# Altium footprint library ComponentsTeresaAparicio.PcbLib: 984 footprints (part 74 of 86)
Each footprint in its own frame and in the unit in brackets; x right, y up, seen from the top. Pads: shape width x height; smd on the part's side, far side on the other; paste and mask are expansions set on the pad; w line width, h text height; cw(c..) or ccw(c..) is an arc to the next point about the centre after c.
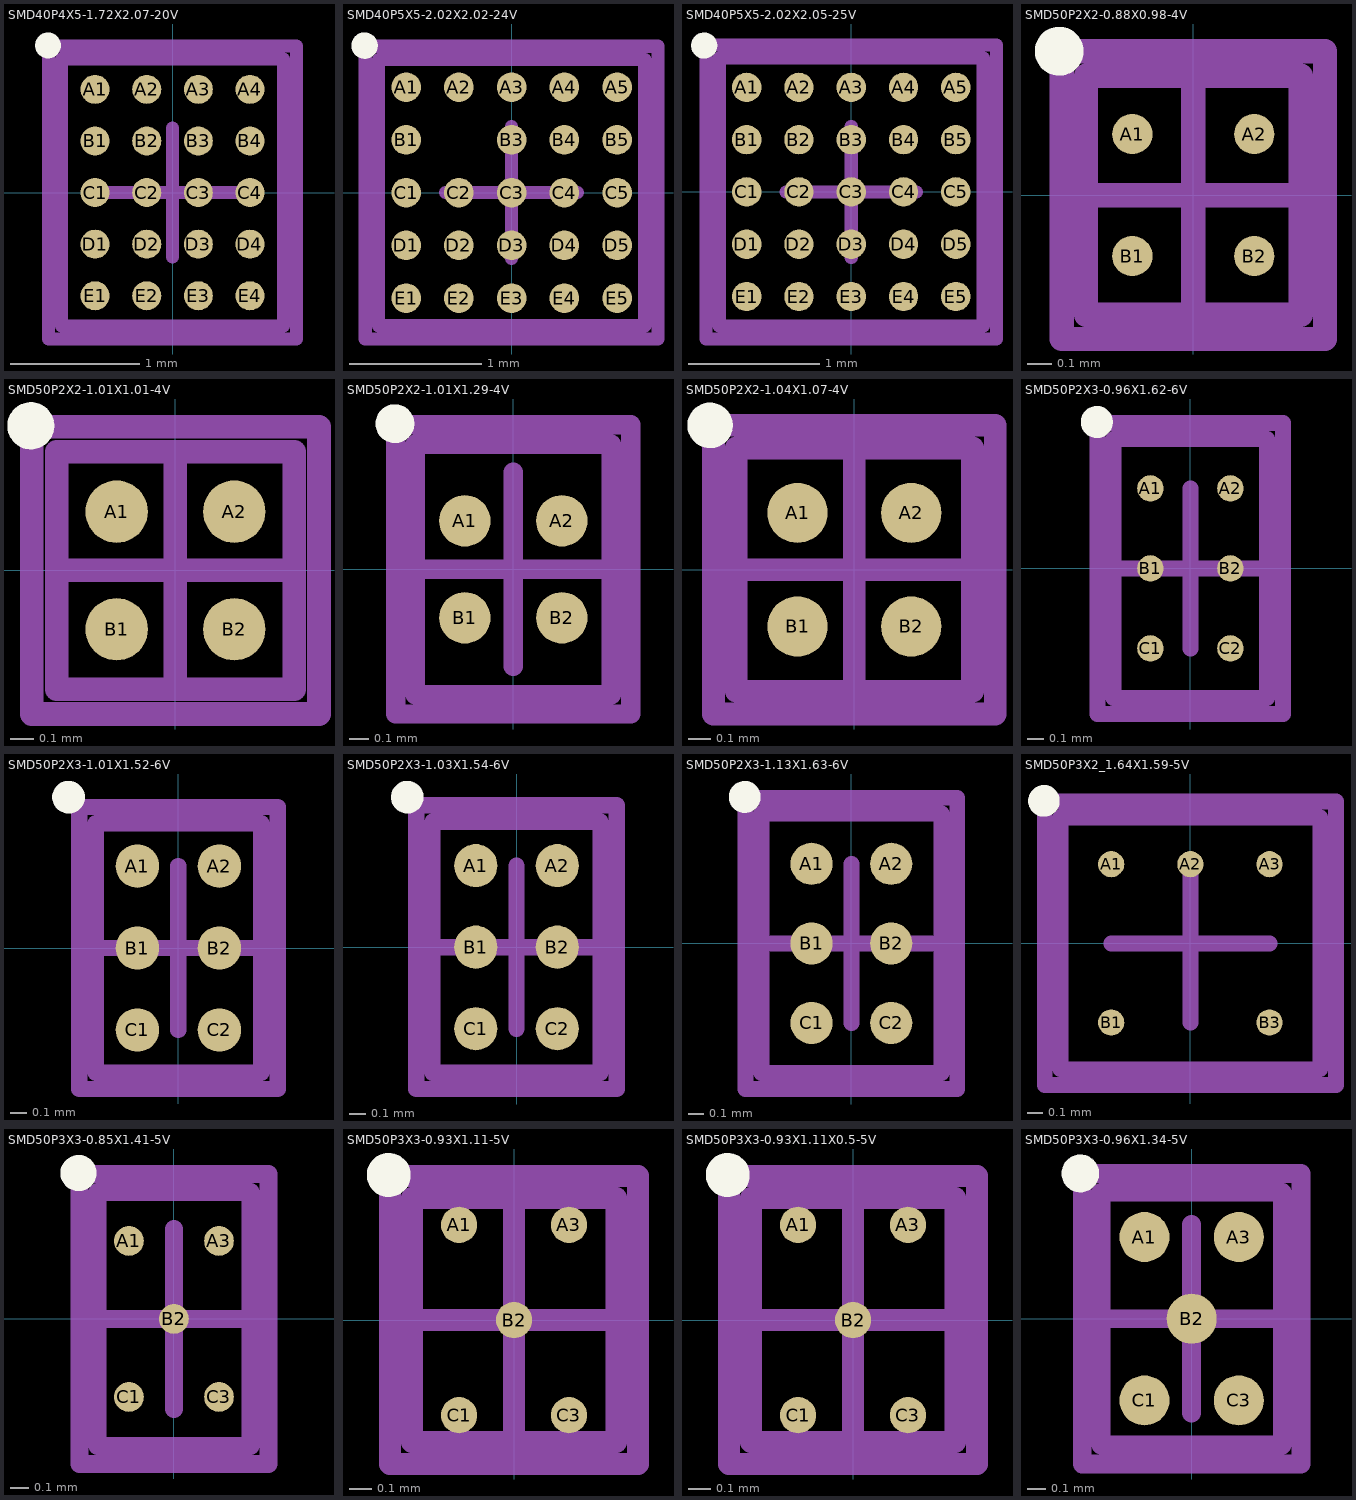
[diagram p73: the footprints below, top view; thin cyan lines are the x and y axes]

## SMD40P4X5-1.72X2.07-20V [mm] "Micro SMD, 20-Leads, Body 2.07x1.72mm, Pitch 0.4mm, NSC Recommended"
height 0.68
pads (20):
  round 0.225 smd paste-0.112 mask+0.05: A1(-0.6,0.8) A2(-0.2,0.8) A3(0.2,0.8) A4(0.6,0.8) B1(-0.6,0.4) B2(-0.2,0.4) B3(0.2,0.4) B4(0.6,0.4) C1(-0.6,0) C2(-0.2,0) C3(0.2,0) C4(0.6,0) D1(-0.6,-0.4) D2(-0.2,-0.4) D3(0.2,-0.4) D4(0.6,-0.4) E1(-0.6,-0.8) E2(-0.2,-0.8) E3(0.2,-0.8) E4(0.6,-0.8)
Top Overlay:
  circle w0.1: c-0.965,1.14 r0.05
Top Paste:
  drawing of 180 lines, arcs and shapes, not listed
Mechanical 13:
  lines w0.1: -0.86,-1.035 0.86,-1.035 0.86,1.035 -0.86,1.035 -0.86,-1.035
Mechanical 15:
  lines w0.1: -0.5,0 0.5,0 ; 0,-0.5 0,0.5 ; -0.96,-1.135 0.96,-1.135 0.96,1.135 -0.96,1.135 -0.96,-1.135
3D body: height 0.68, standoff 0, extent -0.86,-1.035 0.86,1.035

## SMD40P5X5-2.02X2.02-24V [mm] "Micro SMD, 24-Leads, Body 2.02x2.02mm, Pitch 0.4mm, NSC Recommended"
height 0.68
pads (24):
  round 0.225 smd paste-0.112 mask+0.05: A1(-0.8,0.8) A2(-0.4,0.8) A3(0,0.8) A4(0.4,0.8) A5(0.8,0.8) B1(-0.8,0.4) B3(0,0.4) B4(0.4,0.4) B5(0.8,0.4) C1(-0.8,0) C2(-0.4,0) C3(0,0) C4(0.4,0) C5(0.8,0) D1(-0.8,-0.4) D2(-0.4,-0.4) D3(0,-0.4) D4(0.4,-0.4) D5(0.8,-0.4) E1(-0.8,-0.8) E2(-0.4,-0.8) E3(0,-0.8) E4(0.4,-0.8) E5(0.8,-0.8)
Top Overlay:
  circle w0.1: c-1.115,1.115 r0.05
Top Paste:
  drawing of 216 lines, arcs and shapes, not listed
Mechanical 13:
  lines w0.1: -1.01,-1.01 -1.01,1.01 1.01,1.01 1.01,-1.01 -1.01,-1.01
Mechanical 15:
  lines w0.1: -0.5,0 0.5,0 ; 0,-0.5 0,0.5 ; -1.11,-1.11 -1.11,1.11 1.11,1.11 1.11,-1.11 -1.11,-1.11
3D body: height 0.68, standoff 0, extent -1.01,-1.01 1.01,1.01

## SMD40P5X5-2.02X2.05-25V [mm] "Micro SMD, 25-Leads, Body 2.05x2.02mm, Pitch 0.4mm, NSC Recommended"
height 0.68
pads (25):
  round 0.225 smd paste-0.112 mask+0.05: A1(-0.8,0.8) A2(-0.4,0.8) A3(0,0.8) A4(0.4,0.8) A5(0.8,0.8) B1(-0.8,0.4) B2(-0.4,0.4) B3(0,0.4) B4(0.4,0.4) B5(0.8,0.4) C1(-0.8,0) C2(-0.4,0) C3(0,0) C4(0.4,0) C5(0.8,0) D1(-0.8,-0.4) D2(-0.4,-0.4) D3(0,-0.4) D4(0.4,-0.4) D5(0.8,-0.4) E1(-0.8,-0.8) E2(-0.4,-0.8) E3(0,-0.8) E4(0.4,-0.8) E5(0.8,-0.8)
Top Overlay:
  circle w0.1: c-1.125,1.12 r0.05
Top Paste:
  drawing of 225 lines, arcs and shapes, not listed
Mechanical 13:
  lines w0.1: -1.01,-1.025 1.01,-1.025 1.01,1.025 -1.01,1.025 -1.01,-1.025
Mechanical 15:
  lines w0.1: -0.5,0 0.5,0 ; 0,-0.5 0,0.5 ; -1.11,-1.125 1.11,-1.125 1.11,1.125 -1.11,1.125 -1.11,-1.125
3D body: height 0.68, standoff 0, extent -1.009,-1.024 1.009,1.024

## SMD50P2X2-0.88X0.98-4V [mm] "Micro SMD, 4-Leads, Body 0.98x0.88mm, Pitch 0.5mm, NSC Recommended"
height 0.58
pads (4):
  round 0.165 smd paste-0.082 mask+0.05: A1(-0.25,0.25) A2(0.25,0.25) B1(-0.25,-0.25) B2(0.25,-0.25)
Top Overlay:
  circle w0.1: c-0.55,0.59 r0.05
Top Paste:
  circle w0.05: c0.175,0.175 r0.025
  circle w0.05: c0.375,0.375 r0.025
  circle w0.05: c0.175,0.375 r0.025
  circle w0.05: c0.375,0.175 r0.025
  circle w0.05: c0.175,-0.175 r0.025
  circle w0.05: c0.375,-0.375 r0.025
  circle w0.05: c0.375,-0.175 r0.025
  circle w0.05: c0.175,-0.375 r0.025
  circle w0.05: c-0.175,-0.175 r0.025
  circle w0.05: c-0.375,-0.375 r0.025
  circle w0.05: c-0.175,-0.375 r0.025
  circle w0.05: c-0.375,-0.175 r0.025
  circle w0.05: c-0.175,0.175 r0.025
  circle w0.05: c-0.375,0.375 r0.025
  circle w0.05: c-0.375,0.175 r0.025
  circle w0.05: c-0.175,0.375 r0.025
  region: 0.125,0.375 0.125,0.175 0.175,0.175 0.175,0.375
  region: 0.425,0.175 0.425,0.375 0.375,0.375 0.375,0.175
  region: 0.375,0.425 0.175,0.425 0.175,0.375 0.375,0.375
  region: 0.375,0.375 0.175,0.375 0.175,0.175 0.375,0.175
  rectangle: 0.175,0.125 0.375,0.175
  region: 0.375,-0.125 0.175,-0.125 0.175,-0.175 0.375,-0.175
  rectangle: 0.175,-0.425 0.375,-0.375
  region: 0.425,-0.375 0.425,-0.175 0.375,-0.175 0.375,-0.375
  region: 0.375,-0.375 0.375,-0.175 0.175,-0.175 0.175,-0.375
  region: 0.125,-0.175 0.125,-0.375 0.175,-0.375 0.175,-0.175
  region: -0.125,-0.375 -0.125,-0.175 -0.175,-0.175 -0.175,-0.375
  region: -0.425,-0.175 -0.425,-0.375 -0.375,-0.375 -0.375,-0.175
  rectangle: -0.375,-0.425 -0.175,-0.375
  rectangle: -0.375,-0.375 -0.175,-0.175
  region: -0.175,-0.125 -0.375,-0.125 -0.375,-0.175 -0.175,-0.175
  rectangle: -0.375,0.125 -0.175,0.175
  region: -0.175,0.425 -0.375,0.425 -0.375,0.375 -0.175,0.375
  region: -0.425,0.375 -0.425,0.175 -0.375,0.175 -0.375,0.375
  region: -0.375,0.375 -0.375,0.175 -0.175,0.175 -0.175,0.375
  region: -0.125,0.175 -0.125,0.375 -0.175,0.375 -0.175,0.175
Mechanical 13:
  lines w0.1: -0.44,-0.49 -0.44,0.49 0.44,0.49 0.44,-0.49 -0.44,-0.49
Mechanical 15:
  lines w0.1: -0.5,0 0.5,0 ; 0,-0.5 0,0.5 ; -0.54,-0.59 -0.54,0.59 0.54,0.59 0.54,-0.59 -0.54,-0.59
3D body: height 0.58, standoff 0, extent -0.439,-0.489 0.439,0.489

## SMD50P2X2-1.01X1.01-4V [mm] "Micro SMD, 4-Leads, Body 1.01x1.01mm, Pitch 0.5mm, NSC Recommended"
height 0.68
pads (4):
  round 0.265 smd paste-0.132 mask+0.05: A1(-0.25,0.25) A2(0.25,0.25) B1(-0.25,-0.25) B2(0.25,-0.25)
Top Overlay:
  circle w0.1: c-0.615,0.615 r0.05
Top Paste:
  circle w0.05: c-0.35,0.2 r0.025
  circle w0.05: c-0.2,0.35 r0.025
  circle w0.05: c-0.35,0.35 r0.025
  circle w0.05: c-0.2,0.2 r0.025
  circle w0.05: c-0.2,-0.35 r0.025
  circle w0.05: c-0.35,-0.2 r0.025
  circle w0.05: c-0.35,-0.35 r0.025
  circle w0.05: c-0.2,-0.2 r0.025
  circle w0.05: c0.35,-0.2 r0.025
  circle w0.05: c0.2,-0.35 r0.025
  circle w0.05: c0.35,-0.35 r0.025
  circle w0.05: c0.2,-0.2 r0.025
  circle w0.05: c0.2,0.35 r0.025
  circle w0.05: c0.35,0.2 r0.025
  circle w0.05: c0.35,0.35 r0.025
  circle w0.05: c0.2,0.2 r0.025
  region: -0.2,0.35 -0.2,0.2 -0.15,0.2 -0.15,0.35
  rectangle: -0.35,0.35 -0.2,0.4
  region: -0.35,0.2 -0.35,0.35 -0.4,0.35 -0.4,0.2
  region: -0.2,0.2 -0.35,0.2 -0.35,0.15 -0.2,0.15
  rectangle: -0.35,0.2 -0.2,0.35
  rectangle: -0.35,-0.2 -0.2,-0.15
  region: -0.35,-0.35 -0.35,-0.2 -0.4,-0.2 -0.4,-0.35
  region: -0.2,-0.35 -0.35,-0.35 -0.35,-0.4 -0.2,-0.4
  region: -0.2,-0.2 -0.2,-0.35 -0.15,-0.35 -0.15,-0.2
  region: -0.2,-0.35 -0.2,-0.2 -0.35,-0.2 -0.35,-0.35
  region: 0.2,-0.35 0.2,-0.2 0.15,-0.2 0.15,-0.35
  region: 0.35,-0.35 0.2,-0.35 0.2,-0.4 0.35,-0.4
  region: 0.35,-0.2 0.35,-0.35 0.4,-0.35 0.4,-0.2
  rectangle: 0.2,-0.2 0.35,-0.15
  region: 0.35,-0.2 0.2,-0.2 0.2,-0.35 0.35,-0.35
  region: 0.35,0.2 0.2,0.2 0.2,0.15 0.35,0.15
  region: 0.35,0.35 0.35,0.2 0.4,0.2 0.4,0.35
  rectangle: 0.2,0.35 0.35,0.4
  region: 0.2,0.2 0.2,0.35 0.15,0.35 0.15,0.2
  region: 0.2,0.35 0.2,0.2 0.35,0.2 0.35,0.35
Mechanical 13:
  lines w0.1: -0.505,-0.505 -0.505,0.505 0.505,0.505 0.505,-0.505 -0.505,-0.505
Mechanical 15:
  lines w0.1: -0.5,0 0.5,0 ; 0,-0.5 0,0.5 ; -0.61,-0.61 -0.61,0.61 0.61,0.61 0.61,-0.61 -0.61,-0.61
3D body: height 0.68, standoff 0, extent -0.504,-0.504 0.504,0.504

## SMD50P2X2-1.01X1.29-4V [mm] "Micro SMD, 4-Leads, Body 1.29x1.01mm, Pitch 0.5mm, NSC Recommended"
height 0.68
pads (4):
  round 0.265 smd paste-0.132 mask+0.05: A1(-0.25,0.25) A2(0.25,0.25) B1(-0.25,-0.25) B2(0.25,-0.25)
Top Overlay:
  circle w0.1: c-0.61,0.75 r0.05
Top Paste:
  circle w0.05: c-0.35,0.2 r0.025
  circle w0.05: c-0.2,0.35 r0.025
  circle w0.05: c-0.35,0.35 r0.025
  circle w0.05: c-0.2,0.2 r0.025
  circle w0.05: c-0.2,-0.35 r0.025
  circle w0.05: c-0.35,-0.2 r0.025
  circle w0.05: c-0.35,-0.35 r0.025
  circle w0.05: c-0.2,-0.2 r0.025
  circle w0.05: c0.35,-0.2 r0.025
  circle w0.05: c0.2,-0.35 r0.025
  circle w0.05: c0.35,-0.35 r0.025
  circle w0.05: c0.2,-0.2 r0.025
  circle w0.05: c0.2,0.35 r0.025
  circle w0.05: c0.35,0.2 r0.025
  circle w0.05: c0.35,0.35 r0.025
  circle w0.05: c0.2,0.2 r0.025
  region: -0.2,0.35 -0.2,0.2 -0.15,0.2 -0.15,0.35
  rectangle: -0.35,0.35 -0.2,0.4
  region: -0.35,0.2 -0.35,0.35 -0.4,0.35 -0.4,0.2
  region: -0.2,0.2 -0.35,0.2 -0.35,0.15 -0.2,0.15
  rectangle: -0.35,0.2 -0.2,0.35
  rectangle: -0.35,-0.2 -0.2,-0.15
  region: -0.35,-0.35 -0.35,-0.2 -0.4,-0.2 -0.4,-0.35
  region: -0.2,-0.35 -0.35,-0.35 -0.35,-0.4 -0.2,-0.4
  region: -0.2,-0.2 -0.2,-0.35 -0.15,-0.35 -0.15,-0.2
  region: -0.2,-0.35 -0.2,-0.2 -0.35,-0.2 -0.35,-0.35
  region: 0.2,-0.35 0.2,-0.2 0.15,-0.2 0.15,-0.35
  region: 0.35,-0.35 0.2,-0.35 0.2,-0.4 0.35,-0.4
  region: 0.35,-0.2 0.35,-0.35 0.4,-0.35 0.4,-0.2
  rectangle: 0.2,-0.2 0.35,-0.15
  region: 0.35,-0.2 0.2,-0.2 0.2,-0.35 0.35,-0.35
  region: 0.35,0.2 0.2,0.2 0.2,0.15 0.35,0.15
  region: 0.35,0.35 0.35,0.2 0.4,0.2 0.4,0.35
  rectangle: 0.2,0.35 0.35,0.4
  region: 0.2,0.2 0.2,0.35 0.15,0.35 0.15,0.2
  region: 0.2,0.35 0.2,0.2 0.35,0.2 0.35,0.35
Mechanical 13:
  lines w0.1: -0.505,-0.645 -0.505,0.645 0.505,0.645 0.505,-0.645 -0.505,-0.645
Mechanical 15:
  lines w0.1: -0.5,0 0.5,0 ; 0,-0.5 0,0.5 ; -0.605,-0.745 -0.605,0.745 0.605,0.745 0.605,-0.745 -0.605,-0.745
3D body: height 0.68, standoff 0, extent -0.504,-0.644 0.504,0.644

## SMD50P2X2-1.04X1.07-4V [mm] "Micro SMD, 4-Leads, Body 1.07x1.04mm, Pitch 0.5mm, NSC Recommended"
height 0.68
pads (4):
  round 0.265 smd paste-0.132 mask+0.05: A1(-0.25,0.25) A2(0.25,0.25) B1(-0.25,-0.25) B2(0.25,-0.25)
Top Overlay:
  circle w0.1: c-0.635,0.635 r0.05
Top Paste:
  circle w0.05: c0.2,0.2 r0.025
  circle w0.05: c0.35,0.35 r0.025
  circle w0.05: c0.35,0.2 r0.025
  circle w0.05: c0.2,0.35 r0.025
  circle w0.05: c0.2,-0.2 r0.025
  circle w0.05: c0.35,-0.35 r0.025
  circle w0.05: c0.2,-0.35 r0.025
  circle w0.05: c0.35,-0.2 r0.025
  circle w0.05: c-0.2,-0.2 r0.025
  circle w0.05: c-0.35,-0.35 r0.025
  circle w0.05: c-0.35,-0.2 r0.025
  circle w0.05: c-0.2,-0.35 r0.025
  circle w0.05: c-0.2,0.2 r0.025
  circle w0.05: c-0.35,0.35 r0.025
  circle w0.05: c-0.2,0.35 r0.025
  circle w0.05: c-0.35,0.2 r0.025
  region: 0.2,0.35 0.2,0.2 0.35,0.2 0.35,0.35
  region: 0.2,0.2 0.2,0.35 0.15,0.35 0.15,0.2
  rectangle: 0.2,0.35 0.35,0.4
  region: 0.35,0.35 0.35,0.2 0.4,0.2 0.4,0.35
  region: 0.35,0.2 0.2,0.2 0.2,0.15 0.35,0.15
  region: 0.35,-0.2 0.2,-0.2 0.2,-0.35 0.35,-0.35
  rectangle: 0.2,-0.2 0.35,-0.15
  region: 0.35,-0.2 0.35,-0.35 0.4,-0.35 0.4,-0.2
  region: 0.35,-0.35 0.2,-0.35 0.2,-0.4 0.35,-0.4
  region: 0.2,-0.35 0.2,-0.2 0.15,-0.2 0.15,-0.35
  region: -0.2,-0.35 -0.2,-0.2 -0.35,-0.2 -0.35,-0.35
  region: -0.2,-0.2 -0.2,-0.35 -0.15,-0.35 -0.15,-0.2
  region: -0.2,-0.35 -0.35,-0.35 -0.35,-0.4 -0.2,-0.4
  region: -0.35,-0.35 -0.35,-0.2 -0.4,-0.2 -0.4,-0.35
  rectangle: -0.35,-0.2 -0.2,-0.15
  rectangle: -0.35,0.2 -0.2,0.35
  region: -0.2,0.2 -0.35,0.2 -0.35,0.15 -0.2,0.15
  region: -0.35,0.2 -0.35,0.35 -0.4,0.35 -0.4,0.2
  rectangle: -0.35,0.35 -0.2,0.4
  region: -0.2,0.35 -0.2,0.2 -0.15,0.2 -0.15,0.35
Mechanical 13:
  lines w0.1: -0.52,-0.535 0.52,-0.535 0.52,0.535 -0.52,0.535 -0.52,-0.535
Mechanical 15:
  lines w0.1: -0.5,0 0.5,0 ; 0,-0.5 0,0.5 ; -0.62,-0.635 0.62,-0.635 0.62,0.635 -0.62,0.635 -0.62,-0.635
3D body: height 0.68, standoff 0, extent -0.519,-0.534 0.519,0.534

## SMD50P2X3-0.96X1.62-6V [mm] "Micro SMD, 6-Leads, Body 1.62x0.96mm, Pitch 0.5mm, NSC Recommended"
height 0.58
pads (6):
  round 0.165 smd paste-0.082 mask+0.05: A1(-0.25,0.5) A2(0.25,0.5) B1(-0.25,0) B2(0.25,0) C1(-0.25,-0.5) C2(0.25,-0.5)
Top Overlay:
  circle w0.1: c-0.585,0.915 r0.05
Top Paste:
  circle w0.05: c-0.175,0.425 r0.025
  circle w0.05: c-0.375,0.625 r0.025
  circle w0.05: c-0.175,0.625 r0.025
  circle w0.05: c-0.375,0.425 r0.025
  circle w0.05: c0.375,0.425 r0.025
  circle w0.05: c0.175,0.625 r0.025
  circle w0.05: c0.375,0.625 r0.025
  circle w0.05: c0.175,0.425 r0.025
  circle w0.05: c-0.175,-0.1 r0.025
  circle w0.05: c-0.375,0.1 r0.025
  circle w0.05: c-0.175,0.1 r0.025
  circle w0.05: c-0.375,-0.1 r0.025
  circle w0.05: c0.375,-0.1 r0.025
  circle w0.05: c0.175,0.1 r0.025
  circle w0.05: c0.375,0.1 r0.025
  circle w0.05: c0.175,-0.1 r0.025
  circle w0.05: c-0.175,-0.625 r0.025
  circle w0.05: c-0.375,-0.425 r0.025
  circle w0.05: c-0.175,-0.425 r0.025
  circle w0.05: c-0.375,-0.625 r0.025
  circle w0.05: c0.375,-0.625 r0.025
  circle w0.05: c0.175,-0.425 r0.025
  circle w0.05: c0.375,-0.425 r0.025
  circle w0.05: c0.175,-0.625 r0.025
  region: -0.175,0.625 -0.175,0.425 -0.125,0.425 -0.125,0.625
  region: -0.375,0.425 -0.375,0.625 -0.425,0.625 -0.425,0.425
  rectangle: -0.375,0.625 -0.175,0.675
  rectangle: -0.375,0.425 -0.175,0.625
  region: -0.175,0.425 -0.375,0.425 -0.375,0.375 -0.175,0.375
  region: 0.375,0.625 0.375,0.425 0.425,0.425 0.425,0.625
  region: 0.175,0.425 0.175,0.625 0.125,0.625 0.125,0.425
  rectangle: 0.175,0.625 0.375,0.675
  rectangle: 0.175,0.425 0.375,0.625
  region: 0.375,0.425 0.175,0.425 0.175,0.375 0.375,0.375
  region: -0.175,0.1 -0.175,-0.1 -0.125,-0.1 -0.125,0.1
  region: -0.375,-0.1 -0.375,0.1 -0.425,0.1 -0.425,-0.1
  rectangle: -0.375,0.1 -0.175,0.15
  rectangle: -0.375,-0.1 -0.175,0.1
  region: -0.175,-0.1 -0.375,-0.1 -0.375,-0.15 -0.175,-0.15
  region: 0.375,0.1 0.375,-0.1 0.425,-0.1 0.425,0.1
  region: 0.175,-0.1 0.175,0.1 0.125,0.1 0.125,-0.1
  rectangle: 0.175,0.1 0.375,0.15
  rectangle: 0.175,-0.1 0.375,0.1
  region: 0.375,-0.1 0.175,-0.1 0.175,-0.15 0.375,-0.15
  region: -0.175,-0.425 -0.175,-0.625 -0.125,-0.625 -0.125,-0.425
  region: -0.375,-0.625 -0.375,-0.425 -0.425,-0.425 -0.425,-0.625
  rectangle: -0.375,-0.425 -0.175,-0.375
  rectangle: -0.375,-0.625 -0.175,-0.425
  region: -0.175,-0.625 -0.375,-0.625 -0.375,-0.675 -0.175,-0.675
  region: 0.375,-0.425 0.375,-0.625 0.425,-0.625 0.425,-0.425
  region: 0.175,-0.625 0.175,-0.425 0.125,-0.425 0.125,-0.625
  rectangle: 0.175,-0.425 0.375,-0.375
  rectangle: 0.175,-0.625 0.375,-0.425
  region: 0.375,-0.625 0.175,-0.625 0.175,-0.675 0.375,-0.675
Mechanical 13:
  lines w0.1: -0.48,-0.81 -0.48,0.81 0.48,0.81 0.48,-0.81 -0.48,-0.81
Mechanical 15:
  lines w0.1: -0.5,0 0.5,0 ; 0,-0.5 0,0.5 ; -0.58,-0.91 -0.58,0.91 0.58,0.91 0.58,-0.91 -0.58,-0.91
3D body: height 0.58, standoff 0, extent -0.48,-0.81 0.48,0.81

## SMD50P2X3-1.01X1.52-6V [mm] "Micro SMD, 6-Leads, Body 1.52x1.01mm, Pitch 0.5mm, NSC Recommended"
height 1.05
pads (6):
  round 0.265 smd paste-0.132 mask+0.05: A1(-0.25,0.5) A2(0.25,0.5) B1(-0.25,0) B2(0.25,0) C1(-0.25,-0.5) C2(0.25,-0.5)
Top Overlay:
  circle w0.1: c-0.67,0.92 r0.05
Top Paste:
  circle w0.05: c0.2,0.6 r0.025
  circle w0.05: c0.35,0.45 r0.025
  circle w0.05: c0.35,0.6 r0.025
  circle w0.05: c0.2,0.45 r0.025
  circle w0.05: c0.35,-0.45 r0.025
  circle w0.05: c0.2,-0.6 r0.025
  circle w0.05: c0.35,-0.6 r0.025
  circle w0.05: c0.2,-0.45 r0.025
  circle w0.05: c-0.2,-0.6 r0.025
  circle w0.05: c-0.35,-0.45 r0.025
  circle w0.05: c-0.35,-0.6 r0.025
  circle w0.05: c-0.2,-0.45 r0.025
  circle w0.05: c-0.35,0.45 r0.025
  circle w0.05: c-0.2,0.6 r0.025
  circle w0.05: c-0.35,0.6 r0.025
  circle w0.05: c-0.2,0.45 r0.025
  circle w0.05: c-0.2,-0.075 r0.025
  circle w0.05: c-0.35,0.075 r0.025
  circle w0.05: c-0.2,0.075 r0.025
  circle w0.05: c-0.35,-0.075 r0.025
  circle w0.05: c0.2,0.075 r0.025
  circle w0.05: c0.35,-0.075 r0.025
  circle w0.05: c0.2,-0.075 r0.025
  circle w0.05: c0.35,0.075 r0.025
  region: 0.35,0.45 0.2,0.45 0.2,0.4 0.35,0.4
  region: 0.35,0.6 0.35,0.45 0.4,0.45 0.4,0.6
  rectangle: 0.2,0.6 0.35,0.65
  region: 0.2,0.45 0.2,0.6 0.15,0.6 0.15,0.45
  region: 0.2,0.6 0.2,0.45 0.35,0.45 0.35,0.6
  region: 0.2,-0.6 0.2,-0.45 0.15,-0.45 0.15,-0.6
  region: 0.35,-0.6 0.2,-0.6 0.2,-0.65 0.35,-0.65
  region: 0.35,-0.45 0.35,-0.6 0.4,-0.6 0.4,-0.45
  rectangle: 0.2,-0.45 0.35,-0.4
  region: 0.35,-0.45 0.2,-0.45 0.2,-0.6 0.35,-0.6
  rectangle: -0.35,-0.45 -0.2,-0.4
  region: -0.35,-0.6 -0.35,-0.45 -0.4,-0.45 -0.4,-0.6
  region: -0.2,-0.6 -0.35,-0.6 -0.35,-0.65 -0.2,-0.65
  region: -0.2,-0.45 -0.2,-0.6 -0.15,-0.6 -0.15,-0.45
  region: -0.2,-0.6 -0.2,-0.45 -0.35,-0.45 -0.35,-0.6
  region: -0.2,0.6 -0.2,0.45 -0.15,0.45 -0.15,0.6
  rectangle: -0.35,0.6 -0.2,0.65
  region: -0.35,0.45 -0.35,0.6 -0.4,0.6 -0.4,0.45
  region: -0.2,0.45 -0.35,0.45 -0.35,0.4 -0.2,0.4
  rectangle: -0.35,0.45 -0.2,0.6
  rectangle: -0.35,-0.075 -0.2,0.075
  region: -0.2,-0.075 -0.35,-0.075 -0.35,-0.125 -0.2,-0.125
  region: -0.35,-0.075 -0.35,0.075 -0.4,0.075 -0.4,-0.075
  rectangle: -0.35,0.075 -0.2,0.125
  region: -0.2,0.075 -0.2,-0.075 -0.15,-0.075 -0.15,0.075
  region: 0.35,0.075 0.2,0.075 0.2,-0.075 0.35,-0.075
  rectangle: 0.2,0.075 0.35,0.125
  region: 0.35,0.075 0.35,-0.075 0.4,-0.075 0.4,0.075
  region: 0.35,-0.075 0.2,-0.075 0.2,-0.125 0.35,-0.125
  region: 0.2,-0.075 0.2,0.075 0.15,0.075 0.15,-0.075
Mechanical 13:
  lines w0.1: -0.505,-0.76 0.505,-0.76 0.505,0.76 -0.505,0.76 -0.505,-0.76
Mechanical 15:
  lines w0.1: -0.5,0 0.5,0 ; 0,-0.5 0,0.5 ; -0.605,-0.86 0.605,-0.86 0.605,0.86 -0.605,0.86 -0.605,-0.86
3D body: height 1.05, standoff 0, extent -0.504,-0.759 0.504,0.759

## SMD50P2X3-1.03X1.54-6V [mm] "Micro SMD, 6-Leads, Body 1.54x1.03mm, Pitch 0.5mm, NSC Recommended"
height 0.68
pads (6):
  round 0.265 smd paste-0.132 mask+0.05: A1(-0.25,0.5) A2(0.25,0.5) B1(-0.25,0) B2(0.25,0) C1(-0.25,-0.5) C2(0.25,-0.5)
Top Overlay:
  circle w0.1: c-0.67,0.92 r0.05
Top Paste:
  circle w0.05: c0.2,0.6 r0.025
  circle w0.05: c0.35,0.45 r0.025
  circle w0.05: c0.35,0.6 r0.025
  circle w0.05: c0.2,0.45 r0.025
  circle w0.05: c0.35,-0.45 r0.025
  circle w0.05: c0.2,-0.6 r0.025
  circle w0.05: c0.35,-0.6 r0.025
  circle w0.05: c0.2,-0.45 r0.025
  circle w0.05: c-0.2,-0.6 r0.025
  circle w0.05: c-0.35,-0.45 r0.025
  circle w0.05: c-0.35,-0.6 r0.025
  circle w0.05: c-0.2,-0.45 r0.025
  circle w0.05: c-0.35,0.45 r0.025
  circle w0.05: c-0.2,0.6 r0.025
  circle w0.05: c-0.35,0.6 r0.025
  circle w0.05: c-0.2,0.45 r0.025
  circle w0.05: c-0.2,-0.075 r0.025
  circle w0.05: c-0.35,0.075 r0.025
  circle w0.05: c-0.2,0.075 r0.025
  circle w0.05: c-0.35,-0.075 r0.025
  circle w0.05: c0.2,0.075 r0.025
  circle w0.05: c0.35,-0.075 r0.025
  circle w0.05: c0.2,-0.075 r0.025
  circle w0.05: c0.35,0.075 r0.025
  region: 0.35,0.45 0.2,0.45 0.2,0.4 0.35,0.4
  region: 0.35,0.6 0.35,0.45 0.4,0.45 0.4,0.6
  rectangle: 0.2,0.6 0.35,0.65
  region: 0.2,0.45 0.2,0.6 0.15,0.6 0.15,0.45
  region: 0.2,0.6 0.2,0.45 0.35,0.45 0.35,0.6
  region: 0.2,-0.6 0.2,-0.45 0.15,-0.45 0.15,-0.6
  region: 0.35,-0.6 0.2,-0.6 0.2,-0.65 0.35,-0.65
  region: 0.35,-0.45 0.35,-0.6 0.4,-0.6 0.4,-0.45
  rectangle: 0.2,-0.45 0.35,-0.4
  region: 0.35,-0.45 0.2,-0.45 0.2,-0.6 0.35,-0.6
  rectangle: -0.35,-0.45 -0.2,-0.4
  region: -0.35,-0.6 -0.35,-0.45 -0.4,-0.45 -0.4,-0.6
  region: -0.2,-0.6 -0.35,-0.6 -0.35,-0.65 -0.2,-0.65
  region: -0.2,-0.45 -0.2,-0.6 -0.15,-0.6 -0.15,-0.45
  region: -0.2,-0.6 -0.2,-0.45 -0.35,-0.45 -0.35,-0.6
  region: -0.2,0.6 -0.2,0.45 -0.15,0.45 -0.15,0.6
  rectangle: -0.35,0.6 -0.2,0.65
  region: -0.35,0.45 -0.35,0.6 -0.4,0.6 -0.4,0.45
  region: -0.2,0.45 -0.35,0.45 -0.35,0.4 -0.2,0.4
  rectangle: -0.35,0.45 -0.2,0.6
  rectangle: -0.35,-0.075 -0.2,0.075
  region: -0.2,-0.075 -0.35,-0.075 -0.35,-0.125 -0.2,-0.125
  region: -0.35,-0.075 -0.35,0.075 -0.4,0.075 -0.4,-0.075
  rectangle: -0.35,0.075 -0.2,0.125
  region: -0.2,0.075 -0.2,-0.075 -0.15,-0.075 -0.15,0.075
  region: 0.35,0.075 0.2,0.075 0.2,-0.075 0.35,-0.075
  rectangle: 0.2,0.075 0.35,0.125
  region: 0.35,0.075 0.35,-0.075 0.4,-0.075 0.4,0.075
  region: 0.35,-0.075 0.2,-0.075 0.2,-0.125 0.35,-0.125
  region: 0.2,-0.075 0.2,0.075 0.15,0.075 0.15,-0.075
Mechanical 13:
  lines w0.1: -0.515,-0.77 0.515,-0.77 0.515,0.77 -0.515,0.77 -0.515,-0.77
Mechanical 15:
  lines w0.1: -0.5,0 0.5,0 ; 0,-0.5 0,0.5 ; -0.615,-0.87 0.615,-0.87 0.615,0.87 -0.615,0.87 -0.615,-0.87
3D body: height 0.68, standoff 0, extent -0.514,-0.769 0.514,0.769

## SMD50P2X3-1.13X1.63-6V [mm] "Micro SMD, 6-Leads, Body 1.63x1.13mm, Pitch 0.5mm, NSC Recommended"
height 0.4
pads (6):
  round 0.265 smd paste-0.132 mask+0.05: A1(-0.25,0.5) A2(0.25,0.5) B1(-0.25,0) B2(0.25,0) C1(-0.25,-0.5) C2(0.25,-0.5)
Top Overlay:
  circle w0.1: c-0.67,0.92 r0.05
Top Paste:
  circle w0.05: c0.35,0.075 r0.025
  circle w0.05: c0.2,-0.075 r0.025
  circle w0.05: c0.35,-0.075 r0.025
  circle w0.05: c0.2,0.075 r0.025
  circle w0.05: c-0.35,-0.075 r0.025
  circle w0.05: c-0.2,0.075 r0.025
  circle w0.05: c-0.35,0.075 r0.025
  circle w0.05: c-0.2,-0.075 r0.025
  circle w0.05: c-0.2,0.45 r0.025
  circle w0.05: c-0.35,0.6 r0.025
  circle w0.05: c-0.2,0.6 r0.025
  circle w0.05: c-0.35,0.45 r0.025
  circle w0.05: c-0.2,-0.45 r0.025
  circle w0.05: c-0.35,-0.6 r0.025
  circle w0.05: c-0.35,-0.45 r0.025
  circle w0.05: c-0.2,-0.6 r0.025
  circle w0.05: c0.2,-0.45 r0.025
  circle w0.05: c0.35,-0.6 r0.025
  circle w0.05: c0.2,-0.6 r0.025
  circle w0.05: c0.35,-0.45 r0.025
  circle w0.05: c0.2,0.45 r0.025
  circle w0.05: c0.35,0.6 r0.025
  circle w0.05: c0.35,0.45 r0.025
  circle w0.05: c0.2,0.6 r0.025
  region: 0.2,-0.075 0.2,0.075 0.15,0.075 0.15,-0.075
  region: 0.35,-0.075 0.2,-0.075 0.2,-0.125 0.35,-0.125
  region: 0.35,0.075 0.35,-0.075 0.4,-0.075 0.4,0.075
  rectangle: 0.2,0.075 0.35,0.125
  region: 0.35,0.075 0.2,0.075 0.2,-0.075 0.35,-0.075
  region: -0.2,0.075 -0.2,-0.075 -0.15,-0.075 -0.15,0.075
  rectangle: -0.35,0.075 -0.2,0.125
  region: -0.35,-0.075 -0.35,0.075 -0.4,0.075 -0.4,-0.075
  region: -0.2,-0.075 -0.35,-0.075 -0.35,-0.125 -0.2,-0.125
  rectangle: -0.35,-0.075 -0.2,0.075
  rectangle: -0.35,0.45 -0.2,0.6
  region: -0.2,0.45 -0.35,0.45 -0.35,0.4 -0.2,0.4
  region: -0.35,0.45 -0.35,0.6 -0.4,0.6 -0.4,0.45
  rectangle: -0.35,0.6 -0.2,0.65
  region: -0.2,0.6 -0.2,0.45 -0.15,0.45 -0.15,0.6
  region: -0.2,-0.6 -0.2,-0.45 -0.35,-0.45 -0.35,-0.6
  region: -0.2,-0.45 -0.2,-0.6 -0.15,-0.6 -0.15,-0.45
  region: -0.2,-0.6 -0.35,-0.6 -0.35,-0.65 -0.2,-0.65
  region: -0.35,-0.6 -0.35,-0.45 -0.4,-0.45 -0.4,-0.6
  rectangle: -0.35,-0.45 -0.2,-0.4
  region: 0.35,-0.45 0.2,-0.45 0.2,-0.6 0.35,-0.6
  rectangle: 0.2,-0.45 0.35,-0.4
  region: 0.35,-0.45 0.35,-0.6 0.4,-0.6 0.4,-0.45
  region: 0.35,-0.6 0.2,-0.6 0.2,-0.65 0.35,-0.65
  region: 0.2,-0.6 0.2,-0.45 0.15,-0.45 0.15,-0.6
  region: 0.2,0.6 0.2,0.45 0.35,0.45 0.35,0.6
  region: 0.2,0.45 0.2,0.6 0.15,0.6 0.15,0.45
  rectangle: 0.2,0.6 0.35,0.65
  region: 0.35,0.6 0.35,0.45 0.4,0.45 0.4,0.6
  region: 0.35,0.45 0.2,0.45 0.2,0.4 0.35,0.4
Mechanical 13:
  lines w0.1: -0.565,-0.815 0.565,-0.815 0.565,0.815 -0.565,0.815 -0.565,-0.815
Mechanical 15:
  lines w0.1: -0.5,0 0.5,0 ; 0,-0.5 0,0.5 ; -0.665,-0.915 0.665,-0.915 0.665,0.915 -0.665,0.915 -0.665,-0.915
3D body: height 0.4, standoff 0, extent -0.564,-0.814 0.564,0.814

## SMD50P3X2_1.64X1.59-5V [mm] "Micro SMD, 5-Leads, Body 1.59x1.64mm, Pitch 0.5mm, NSC Recommended"
height 0.58
pads (5):
  round 0.165 smd paste-0.082 mask+0.05: A1(-0.5,0.5) A2(0,0.5) A3(0.5,0.5) B1(-0.5,-0.5) B3(0.5,-0.5)
Top Overlay:
  circle w0.1: c-0.925,0.9 r0.05
Top Paste:
  circle w0.05: c0.625,-0.625 r0.025
  circle w0.05: c0.425,-0.425 r0.025
  circle w0.05: c0.625,-0.425 r0.025
  circle w0.05: c0.425,-0.625 r0.025
  circle w0.05: c-0.625,-0.625 r0.025
  circle w0.05: c-0.425,-0.425 r0.025
  circle w0.05: c-0.625,-0.425 r0.025
  circle w0.05: c-0.425,-0.625 r0.025
  circle w0.05: c0.625,0.425 r0.025
  circle w0.05: c0.425,0.625 r0.025
  circle w0.05: c0.625,0.625 r0.025
  circle w0.05: c0.425,0.425 r0.025
  circle w0.05: c-0.425,0.425 r0.025
  circle w0.05: c-0.625,0.625 r0.025
  circle w0.05: c-0.425,0.625 r0.025
  circle w0.05: c-0.625,0.425 r0.025
  circle w0.05: c-0.1,0.425 r0.025
  circle w0.05: c0.1,0.625 r0.025
  circle w0.05: c-0.1,0.625 r0.025
  circle w0.05: c0.1,0.425 r0.025
  region: 0.625,-0.425 0.625,-0.625 0.675,-0.625 0.675,-0.425
  region: 0.425,-0.625 0.425,-0.425 0.375,-0.425 0.375,-0.625
  rectangle: 0.425,-0.425 0.625,-0.375
  rectangle: 0.425,-0.625 0.625,-0.425
  region: 0.625,-0.625 0.425,-0.625 0.425,-0.675 0.625,-0.675
  region: -0.425,-0.625 -0.625,-0.625 -0.625,-0.675 -0.425,-0.675
  rectangle: -0.625,-0.625 -0.425,-0.425
  rectangle: -0.625,-0.425 -0.425,-0.375
  region: -0.625,-0.625 -0.625,-0.425 -0.675,-0.425 -0.675,-0.625
  region: -0.425,-0.425 -0.425,-0.625 -0.375,-0.625 -0.375,-0.425
  region: 0.625,0.625 0.625,0.425 0.675,0.425 0.675,0.625
  region: 0.425,0.425 0.425,0.625 0.375,0.625 0.375,0.425
  rectangle: 0.425,0.625 0.625,0.675
  rectangle: 0.425,0.425 0.625,0.625
  region: 0.625,0.425 0.425,0.425 0.425,0.375 0.625,0.375
  region: -0.425,0.625 -0.425,0.425 -0.375,0.425 -0.375,0.625
  region: -0.625,0.425 -0.625,0.625 -0.675,0.625 -0.675,0.425
  rectangle: -0.625,0.625 -0.425,0.675
  rectangle: -0.625,0.425 -0.425,0.625
  region: -0.425,0.425 -0.625,0.425 -0.625,0.375 -0.425,0.375
  region: 0.1,0.425 -0.1,0.425 -0.1,0.375 0.1,0.375
  rectangle: -0.1,0.425 0.1,0.625
  rectangle: -0.1,0.625 0.1,0.675
  region: -0.1,0.425 -0.1,0.625 -0.15,0.625 -0.15,0.425
  region: 0.1,0.625 0.1,0.425 0.15,0.425 0.15,0.625
Mechanical 13:
  lines w0.1: -0.82,-0.795 -0.82,0.795 0.82,0.795 0.82,-0.795 -0.82,-0.795
Mechanical 15:
  lines w0.1: -0.5,0 0.5,0 ; 0,-0.5 0,0.5 ; -0.92,-0.895 0.92,-0.895 0.92,0.895 -0.92,0.895 -0.92,-0.895
3D body: height 0.58, standoff 0, extent -0.819,-0.794 0.819,0.794

## SMD50P3X3-0.85X1.41-5V [mm] "Micro SMD, 5-Leads, Body 1.41x0.85mm, Pitch 0.5mm, NSC Recommended"
height 1
pads (5):
  round 0.165 smd paste-0.082 mask+0.05: A1(-0.25,0.433) A3(0.25,0.433) B2(0,0) C1(-0.25,-0.433) C3(0.25,-0.433)
Top Overlay:
  circle w0.1: c-0.53,0.81 r0.05
Top Paste:
  circle w0.05: c-0.1,-0.1 r0.025
  circle w0.05: c0.1,0.1 r0.025
  circle w0.05: c-0.1,0.1 r0.025
  circle w0.05: c0.1,-0.1 r0.025
  circle w0.05: c0.175,0.358 r0.025
  circle w0.05: c0.375,0.558 r0.025
  circle w0.05: c0.375,0.358 r0.025
  circle w0.05: c0.175,0.558 r0.025
  circle w0.05: c0.175,-0.358 r0.025
  circle w0.05: c0.375,-0.558 r0.025
  circle w0.05: c0.175,-0.558 r0.025
  circle w0.05: c0.375,-0.358 r0.025
  circle w0.05: c-0.175,-0.358 r0.025
  circle w0.05: c-0.375,-0.558 r0.025
  circle w0.05: c-0.375,-0.358 r0.025
  circle w0.05: c-0.175,-0.558 r0.025
  circle w0.05: c-0.175,0.358 r0.025
  circle w0.05: c-0.375,0.558 r0.025
  circle w0.05: c-0.175,0.558 r0.025
  circle w0.05: c-0.375,0.358 r0.025
  region: 0.1,-0.1 -0.1,-0.1 -0.1,-0.15 0.1,-0.15
  rectangle: -0.1,-0.1 0.1,0.1
  rectangle: -0.1,0.1 0.1,0.15
  region: -0.1,-0.1 -0.1,0.1 -0.15,0.1 -0.15,-0.1
  region: 0.1,0.1 0.1,-0.1 0.15,-0.1 0.15,0.1
  region: 0.375,0.358 0.175,0.358 0.175,0.308 0.375,0.308
  rectangle: 0.175,0.558 0.375,0.608
  region: 0.375,0.558 0.375,0.358 0.425,0.358 0.425,0.558
  region: 0.175,0.558 0.175,0.358 0.375,0.358 0.375,0.558
  region: 0.175,0.358 0.175,0.558 0.125,0.558 0.125,0.358
  region: 0.175,-0.558 0.175,-0.358 0.125,-0.358 0.125,-0.558
  region: 0.375,-0.358 0.375,-0.558 0.425,-0.558 0.425,-0.358
  region: 0.375,-0.558 0.175,-0.558 0.175,-0.608 0.375,-0.608
  region: 0.375,-0.358 0.175,-0.358 0.175,-0.558 0.375,-0.558
  rectangle: 0.175,-0.358 0.375,-0.308
  rectangle: -0.375,-0.358 -0.175,-0.308
  region: -0.175,-0.558 -0.375,-0.558 -0.375,-0.608 -0.175,-0.608
  region: -0.375,-0.558 -0.375,-0.358 -0.425,-0.358 -0.425,-0.558
  region: -0.175,-0.558 -0.175,-0.358 -0.375,-0.358 -0.375,-0.558
  region: -0.175,-0.358 -0.175,-0.558 -0.125,-0.558 -0.125,-0.358
  region: -0.175,0.558 -0.175,0.358 -0.125,0.358 -0.125,0.558
  region: -0.375,0.358 -0.375,0.558 -0.425,0.558 -0.425,0.358
  rectangle: -0.375,0.558 -0.175,0.608
  rectangle: -0.375,0.358 -0.175,0.558
  region: -0.175,0.358 -0.375,0.358 -0.375,0.308 -0.175,0.308
Mechanical 13:
  lines w0.1: -0.425,-0.705 0.425,-0.705 0.425,0.705 -0.425,0.705 -0.425,-0.705
Mechanical 15:
  lines w0.1: -0.5,0 0.5,0 ; 0,-0.5 0,0.5 ; -0.525,-0.805 -0.525,0.805 0.525,0.805 0.525,-0.805 -0.525,-0.805
3D body: height 1, standoff 0, extent -0.424,-0.704 0.424,0.704

## SMD50P3X3-0.93X1.11-5V [mm] "Micro SMD, 5-Leads, Body 1.11x0.93mm, Pitch 0.5mm, NSC Recommended"
height 0.95
pads (5):
  round 0.165 smd paste-0.082 mask+0.05: A1(-0.25,0.433) A3(0.25,0.433) B2(0,0) C1(-0.25,-0.433) C3(0.25,-0.433)
Top Overlay:
  circle w0.1: c-0.57,0.66 r0.05
Top Paste:
  circle w0.05: c-0.375,0.358 r0.025
  circle w0.05: c-0.175,0.558 r0.025
  circle w0.05: c-0.375,0.558 r0.025
  circle w0.05: c-0.175,0.358 r0.025
  circle w0.05: c-0.175,-0.558 r0.025
  circle w0.05: c-0.375,-0.358 r0.025
  circle w0.05: c-0.375,-0.558 r0.025
  circle w0.05: c-0.175,-0.358 r0.025
  circle w0.05: c0.375,-0.358 r0.025
  circle w0.05: c0.175,-0.558 r0.025
  circle w0.05: c0.375,-0.558 r0.025
  circle w0.05: c0.175,-0.358 r0.025
  circle w0.05: c0.175,0.558 r0.025
  circle w0.05: c0.375,0.358 r0.025
  circle w0.05: c0.375,0.558 r0.025
  circle w0.05: c0.175,0.358 r0.025
  circle w0.05: c0.1,-0.1 r0.025
  circle w0.05: c-0.1,0.1 r0.025
  circle w0.05: c0.1,0.1 r0.025
  circle w0.05: c-0.1,-0.1 r0.025
  region: -0.175,0.358 -0.375,0.358 -0.375,0.308 -0.175,0.308
  rectangle: -0.375,0.358 -0.175,0.558
  rectangle: -0.375,0.558 -0.175,0.608
  region: -0.375,0.358 -0.375,0.558 -0.425,0.558 -0.425,0.358
  region: -0.175,0.558 -0.175,0.358 -0.125,0.358 -0.125,0.558
  region: -0.175,-0.358 -0.175,-0.558 -0.125,-0.558 -0.125,-0.358
  region: -0.175,-0.558 -0.175,-0.358 -0.375,-0.358 -0.375,-0.558
  region: -0.375,-0.558 -0.375,-0.358 -0.425,-0.358 -0.425,-0.558
  region: -0.175,-0.558 -0.375,-0.558 -0.375,-0.608 -0.175,-0.608
  rectangle: -0.375,-0.358 -0.175,-0.308
  rectangle: 0.175,-0.358 0.375,-0.308
  region: 0.375,-0.358 0.175,-0.358 0.175,-0.558 0.375,-0.558
  region: 0.375,-0.558 0.175,-0.558 0.175,-0.608 0.375,-0.608
  region: 0.375,-0.358 0.375,-0.558 0.425,-0.558 0.425,-0.358
  region: 0.175,-0.558 0.175,-0.358 0.125,-0.358 0.125,-0.558
  region: 0.175,0.358 0.175,0.558 0.125,0.558 0.125,0.358
  region: 0.175,0.558 0.175,0.358 0.375,0.358 0.375,0.558
  region: 0.375,0.558 0.375,0.358 0.425,0.358 0.425,0.558
  rectangle: 0.175,0.558 0.375,0.608
  region: 0.375,0.358 0.175,0.358 0.175,0.308 0.375,0.308
  region: 0.1,0.1 0.1,-0.1 0.15,-0.1 0.15,0.1
  region: -0.1,-0.1 -0.1,0.1 -0.15,0.1 -0.15,-0.1
  rectangle: -0.1,0.1 0.1,0.15
  rectangle: -0.1,-0.1 0.1,0.1
  region: 0.1,-0.1 -0.1,-0.1 -0.1,-0.15 0.1,-0.15
Mechanical 13:
  lines w0.1: -0.465,-0.555 0.465,-0.555 0.465,0.555 -0.465,0.555 -0.465,-0.555
Mechanical 15:
  lines w0.1: -0.5,0 0.5,0 ; 0,-0.5 0,0.5 ; -0.565,-0.655 0.565,-0.655 0.565,0.655 -0.565,0.655 -0.565,-0.655
3D body: height 0.95, standoff 0, extent -0.464,-0.552 0.464,0.557

## SMD50P3X3-0.93X1.11X0.5-5V [mm] "Micro SMD, 5-Leads, Body 1.11x0.93mm, Pitch 0.5mm, NSC Recommended"
height 0.58
pads (5):
  round 0.165 smd paste-0.082 mask+0.05: A1(-0.25,0.433) A3(0.25,0.433) B2(0,0) C1(-0.25,-0.433) C3(0.25,-0.433)
Top Overlay:
  circle w0.1: c-0.57,0.66 r0.05
Top Paste:
  circle w0.05: c-0.375,0.358 r0.025
  circle w0.05: c-0.175,0.558 r0.025
  circle w0.05: c-0.375,0.558 r0.025
  circle w0.05: c-0.175,0.358 r0.025
  circle w0.05: c-0.175,-0.558 r0.025
  circle w0.05: c-0.375,-0.358 r0.025
  circle w0.05: c-0.375,-0.558 r0.025
  circle w0.05: c-0.175,-0.358 r0.025
  circle w0.05: c0.375,-0.358 r0.025
  circle w0.05: c0.175,-0.558 r0.025
  circle w0.05: c0.375,-0.558 r0.025
  circle w0.05: c0.175,-0.358 r0.025
  circle w0.05: c0.175,0.558 r0.025
  circle w0.05: c0.375,0.358 r0.025
  circle w0.05: c0.375,0.558 r0.025
  circle w0.05: c0.175,0.358 r0.025
  circle w0.05: c0.1,-0.1 r0.025
  circle w0.05: c-0.1,0.1 r0.025
  circle w0.05: c0.1,0.1 r0.025
  circle w0.05: c-0.1,-0.1 r0.025
  region: -0.175,0.358 -0.375,0.358 -0.375,0.308 -0.175,0.308
  rectangle: -0.375,0.358 -0.175,0.558
  rectangle: -0.375,0.558 -0.175,0.608
  region: -0.375,0.358 -0.375,0.558 -0.425,0.558 -0.425,0.358
  region: -0.175,0.558 -0.175,0.358 -0.125,0.358 -0.125,0.558
  region: -0.175,-0.358 -0.175,-0.558 -0.125,-0.558 -0.125,-0.358
  region: -0.175,-0.558 -0.175,-0.358 -0.375,-0.358 -0.375,-0.558
  region: -0.375,-0.558 -0.375,-0.358 -0.425,-0.358 -0.425,-0.558
  region: -0.175,-0.558 -0.375,-0.558 -0.375,-0.608 -0.175,-0.608
  rectangle: -0.375,-0.358 -0.175,-0.308
  rectangle: 0.175,-0.358 0.375,-0.308
  region: 0.375,-0.358 0.175,-0.358 0.175,-0.558 0.375,-0.558
  region: 0.375,-0.558 0.175,-0.558 0.175,-0.608 0.375,-0.608
  region: 0.375,-0.358 0.375,-0.558 0.425,-0.558 0.425,-0.358
  region: 0.175,-0.558 0.175,-0.358 0.125,-0.358 0.125,-0.558
  region: 0.175,0.358 0.175,0.558 0.125,0.558 0.125,0.358
  region: 0.175,0.558 0.175,0.358 0.375,0.358 0.375,0.558
  region: 0.375,0.558 0.375,0.358 0.425,0.358 0.425,0.558
  rectangle: 0.175,0.558 0.375,0.608
  region: 0.375,0.358 0.175,0.358 0.175,0.308 0.375,0.308
  region: 0.1,0.1 0.1,-0.1 0.15,-0.1 0.15,0.1
  region: -0.1,-0.1 -0.1,0.1 -0.15,0.1 -0.15,-0.1
  rectangle: -0.1,0.1 0.1,0.15
  rectangle: -0.1,-0.1 0.1,0.1
  region: 0.1,-0.1 -0.1,-0.1 -0.1,-0.15 0.1,-0.15
Mechanical 13:
  lines w0.1: -0.465,-0.555 -0.465,0.555 0.465,0.555 0.465,-0.555 -0.465,-0.555
Mechanical 15:
  lines w0.1: -0.5,0 0.5,0 ; 0,-0.5 0,0.5 ; -0.565,-0.655 -0.565,0.655 0.565,0.655 0.565,-0.655 -0.565,-0.655
3D body: height 0.58, standoff 0, extent -0.464,-0.554 0.464,0.554

## SMD50P3X3-0.96X1.34-5V [mm] "Micro SMD, 5-Leads, Body 1.34x0.96mm, Pitch 0.5mm, NSC Recommended"
height 0.68
pads (5):
  round 0.265 smd paste-0.132 mask+0.05: A1(-0.25,0.433) A3(0.25,0.433) B2(0,0) C1(-0.25,-0.433) C3(0.25,-0.433)
Top Overlay:
  circle w0.1: c-0.59,0.77 r0.05
Top Paste:
  circle w0.05: c-0.2,0.383 r0.025
  circle w0.05: c-0.35,0.533 r0.025
  circle w0.05: c-0.2,0.533 r0.025
  circle w0.05: c-0.35,0.383 r0.025
  circle w0.05: c-0.2,-0.383 r0.025
  circle w0.05: c-0.35,-0.533 r0.025
  circle w0.05: c-0.35,-0.383 r0.025
  circle w0.05: c-0.2,-0.533 r0.025
  circle w0.05: c0.2,-0.383 r0.025
  circle w0.05: c0.35,-0.533 r0.025
  circle w0.05: c0.2,-0.533 r0.025
  circle w0.05: c0.35,-0.383 r0.025
  circle w0.05: c0.2,0.383 r0.025
  circle w0.05: c0.35,0.533 r0.025
  circle w0.05: c0.35,0.383 r0.025
  circle w0.05: c0.2,0.533 r0.025
  circle w0.05: c-0.075,0.075 r0.025
  circle w0.05: c0.075,-0.075 r0.025
  circle w0.05: c0.075,0.075 r0.025
  circle w0.05: c-0.075,-0.075 r0.025
  rectangle: -0.35,0.383 -0.2,0.533
  region: -0.2,0.383 -0.35,0.383 -0.35,0.333 -0.2,0.333
  region: -0.35,0.383 -0.35,0.533 -0.4,0.533 -0.4,0.383
  rectangle: -0.35,0.533 -0.2,0.583
  region: -0.2,0.533 -0.2,0.383 -0.15,0.383 -0.15,0.533
  region: -0.2,-0.533 -0.2,-0.383 -0.35,-0.383 -0.35,-0.533
  region: -0.2,-0.383 -0.2,-0.533 -0.15,-0.533 -0.15,-0.383
  region: -0.2,-0.533 -0.35,-0.533 -0.35,-0.583 -0.2,-0.583
  region: -0.35,-0.533 -0.35,-0.383 -0.4,-0.383 -0.4,-0.533
  rectangle: -0.35,-0.383 -0.2,-0.333
  region: 0.35,-0.383 0.2,-0.383 0.2,-0.533 0.35,-0.533
  rectangle: 0.2,-0.383 0.35,-0.333
  region: 0.35,-0.383 0.35,-0.533 0.4,-0.533 0.4,-0.383
  region: 0.35,-0.533 0.2,-0.533 0.2,-0.583 0.35,-0.583
  region: 0.2,-0.533 0.2,-0.383 0.15,-0.383 0.15,-0.533
  region: 0.2,0.533 0.2,0.383 0.35,0.383 0.35,0.533
  region: 0.2,0.383 0.2,0.533 0.15,0.533 0.15,0.383
  rectangle: 0.2,0.533 0.35,0.583
  region: 0.35,0.533 0.35,0.383 0.4,0.383 0.4,0.533
  region: 0.35,0.383 0.2,0.383 0.2,0.333 0.35,0.333
  region: 0.075,-0.075 -0.075,-0.075 -0.075,-0.125 0.075,-0.125
  region: 0.075,0.075 0.075,-0.075 0.125,-0.075 0.125,0.075
  rectangle: -0.075,0.075 0.075,0.125
  region: -0.075,-0.075 -0.075,0.075 -0.125,0.075 -0.125,-0.075
  region: -0.075,0.075 -0.075,-0.075 0.075,-0.075 0.075,0.075
Mechanical 13:
  lines w0.1: -0.48,-0.67 0.48,-0.67 0.48,0.67 -0.48,0.67 -0.48,-0.67
Mechanical 15:
  lines w0.1: -0.5,0 0.5,0 ; 0,-0.5 0,0.5 ; -0.58,-0.77 0.58,-0.77 0.58,0.77 -0.58,0.77 -0.58,-0.77
3D body: height 0.68, standoff 0, extent -0.479,-0.669 0.479,0.669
